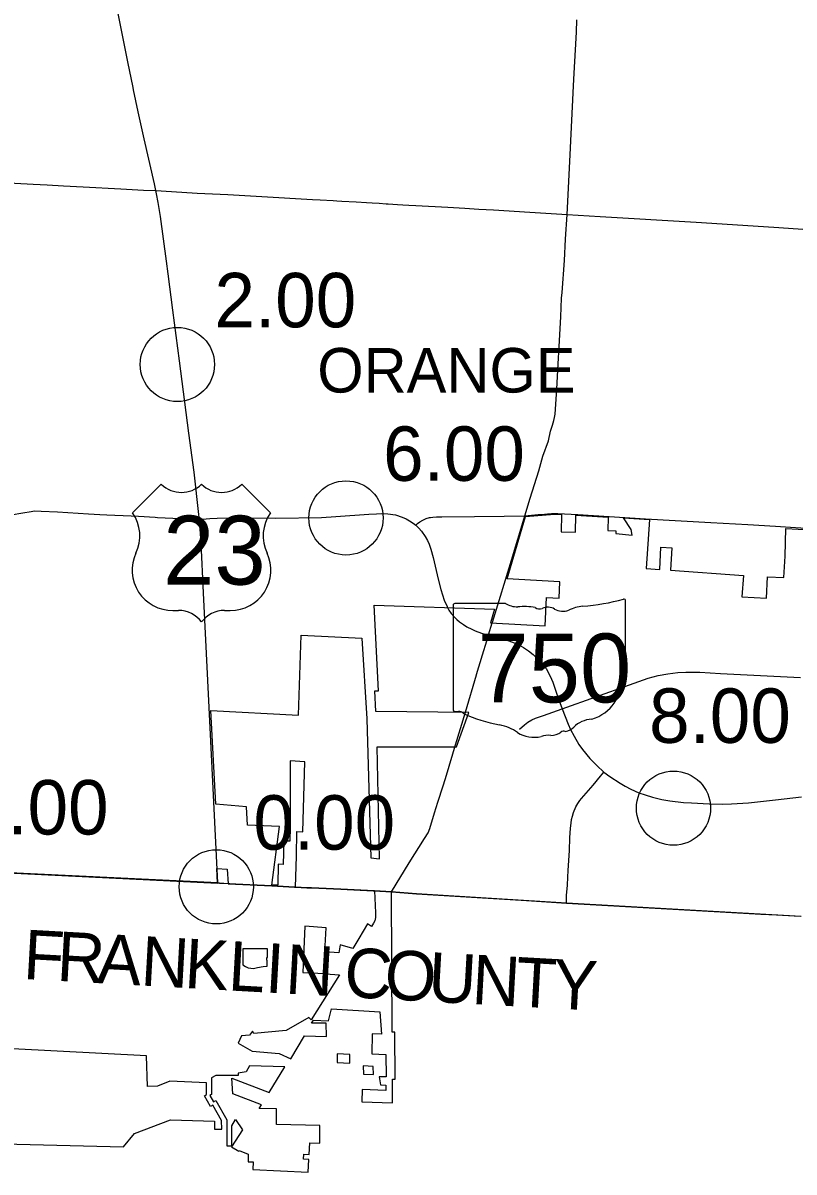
# Model space of a CAD drawing. Extents: x 1597222 to 1925846, y 496284 to 911751.
# Drawn here: x 1820000 to 1835573, y 772839 to 796062 of the extents above; entities that cross this region are included whole.
import ezdxf

# ---------------------------------------------------------------- set-up
doc = ezdxf.new("R2010")
doc.units = 0
for name, color, linetype in [('Default', 7, 'Continuous'), ('GM_X_Adjacent_County_Text', 7, 'Continuous'), ('GM_X_City_Street', 7, 'Continuous'), ('GM_X_Corporation', 7, 'Continuous'), ('GM_X_County', 7, 'Continuous'), ('GM_X_County_Road', 7, 'Continuous'), ('GM_X_State_Route', 7, 'Continuous'), ('GM_X_State_Shield', 7, 'Continuous'), ('GM_X_Township_Road', 7, 'Continuous'), ('GM_X_Township_Text', 7, 'Continuous'), ('GM_X_US_Route', 7, 'Continuous'), ('GM_X_US_Shield', 7, 'Continuous')]:
    doc.layers.add(name, color=color, linetype=linetype)

msp = doc.modelspace()

# ---------------------------------------------------------------- linework, layer by layer
at = {"layer": 'Default'}
for centre in [(1823118, 789161), (1826524, 786059), (1833139, 780193), (1823904, 778604), (1823904, 778604)]:
    msp.add_circle(centre, 750, dxfattribs=at)
at = {"layer": 'GM_X_City_Street'}
for points in [[(1829403, 783698), (1829476, 783942)], [(1829157, 782891), (1829157, 782893), (1829284, 783295), (1829370, 783578), (1829403, 783698)], [(1828738, 781474), (1828935, 782130), (1829157, 782891)], [(1830888, 782204), (1832249, 782689), (1832627, 782818), (1832829, 782872), (1833025, 782905), (1833227, 782932), (1833389, 782939), (1833673, 782939), (1834091, 782912), (1835705, 782831)], [(1830028, 781790), (1830127, 781875), (1830195, 781928), (1830278, 781977), (1830355, 782013), (1830512, 782069), (1830888, 782204)], [(1830981, 778275), (1830981, 778426), (1830998, 778636), (1831007, 778800), (1831013, 778930), (1831036, 779338), (1831048, 779591), (1831061, 779791), (1831069, 779893), (1831081, 779966), (1831097, 780033), (1831121, 780106), (1831168, 780218), (1831205, 780288), (1831244, 780348), (1831278, 780391), (1831372, 780495), (1831514, 780657), (1831665, 780837), (1831734, 780922)], [(1827440, 778500), (1827802, 779087), (1828113, 779577), (1828183, 779692), (1828216, 779780), (1828313, 780101), (1828381, 780311), (1828487, 780643), (1828494, 780666)], [(1823936, 778682), (1823966, 778677), (1824145, 778671)], [(1825505, 778597), (1825506, 778597), (1825736, 778586), (1825825, 778586), (1826422, 778555), (1827074, 778521)], [(1827074, 778521), (1827092, 778520), (1827440, 778500)], [(1827440, 778500), (1827947, 778461), (1830173, 778324)], [(1830173, 778324), (1830981, 778275), (1833959, 778105)], [(1833959, 778105), (1834906, 778051)], [(1834906, 778051), (1835221, 778034)], [(1835221, 778034), (1835694, 778007)]]:
    msp.add_lwpolyline(points, dxfattribs=at)
at = {"layer": 'GM_X_Corporation'}
for points in [[(1818182, 778957), (1823932, 778674), (1823918, 778971), (1824127, 778960), (1824141, 778666), (1825025, 778622), (1825481, 778599), (1825506, 778597), (1825523, 779224), (1825533, 779720), (1825651, 779713), (1825692, 781132), (1825397, 781147), (1825395, 779815), (1825387, 779525), (1825271, 779527), (1825258, 779053), (1825157, 779059), (1825145, 778634), (1825026, 778639), (1825182, 779821), (1824534, 779849), (1824515, 780220), (1823897, 780274), (1823795, 782165), (1825564, 782072), (1825620, 783690), (1826843, 783626), (1826946, 782000), (1827027, 779186), (1827198, 779170), (1827151, 781435), (1828757, 781433), (1829006, 782129), (1827128, 782148), (1827107, 782565), (1827182, 782566), (1827094, 784298), (1829525, 784216), (1829446, 783938), (1830547, 783879), (1830576, 784449), (1830831, 784435), (1830843, 784770), (1829780, 784830), (1830014, 785633), (1830149, 786086), (1830738, 786138), (1830880, 786128), (1830868, 785781), (1831158, 785769), (1831166, 786112), (1831819, 786077), (1831815, 785806), (1831974, 785799), (1831974, 785747), (1832303, 785711), (1832283, 785826), (1832129, 786061), (1832652, 786025), (1832587, 785037), (1832862, 785017), (1832886, 785468), (1833103, 785455), (1833079, 785005), (1834553, 784895), (1834518, 784462), (1835014, 784440), (1835039, 784870), (1835370, 784853), (1835392, 785285), (1835406, 785847), (1835905, 785817)], [(1819605, 773412), (1822027, 773351), (1822253, 773619), (1822982, 773891), (1823867, 773865), (1823869, 773706), (1824013, 773704), (1824009, 773883), (1823832, 774190), (1823788, 774165), (1823663, 774381), (1823707, 774406), (1823707, 774642), (1822967, 774677), (1822717, 774575), (1822517, 774567), (1822492, 775187), (1818880, 775374)]]:
    msp.add_lwpolyline(points, dxfattribs=at)
for points in [[(1824345, 775442), (1824627, 775281), (1825175, 775235), (1825413, 775126), (1825685, 775591), (1826129, 775580), (1826126, 775849), (1825830, 775846), (1825867, 775906), (1826173, 775897), (1826228, 776137), (1827210, 776079), (1827238, 775627), (1827055, 775635), (1827043, 775226), (1827330, 775211), (1827337, 774761), (1827196, 774766), (1827218, 774598), (1827327, 774593), (1827332, 774484), (1826851, 774504), (1826841, 774261), (1827466, 774237), (1827464, 774716), (1827514, 774716), (1827510, 775666), (1827460, 775665), (1827440, 778500), (1827098, 778520), (1827121, 778076), (1827120, 777980), (1827107, 777918), (1827081, 777867), (1827042, 777801), (1826956, 777852), (1826782, 777559), (1826660, 777355), (1826409, 777430), (1826380, 777271), (1826098, 777288), (1826124, 777772), (1825694, 777807), (1825650, 776871), (1826109, 776852), (1826109, 776842), (1826395, 776822), (1825819, 775914), (1825776, 775965), (1825313, 775697), (1824665, 775637), (1824635, 775689), (1824578, 775607), (1824414, 775592)], [(1824442, 777348), (1824442, 777026), (1824494, 776994), (1824548, 776966), (1824656, 776953), (1824740, 776974), (1824853, 776996), (1824934, 777003), (1824934, 777124), (1824922, 777124), (1824922, 777172), (1824942, 777172), (1824942, 777248), (1824942, 777348)], [(1826345, 775056), (1826603, 775041), (1826601, 775212), (1826347, 775231)], [(1823775, 774388), (1823850, 774258), (1823893, 774283), (1824116, 773897), (1824117, 773370), (1824217, 773370), (1824216, 773770), (1824292, 773900), (1824434, 773692), (1824210, 773349), (1824358, 773262), (1824368, 773274), (1824549, 773200), (1824547, 773047), (1824647, 773046), (1824645, 772890), (1825759, 772839), (1825774, 773090), (1825665, 773097), (1825671, 773197), (1825780, 773190), (1825795, 773428), (1825995, 773423), (1825999, 773780), (1825120, 773801), (1825121, 774119), (1824773, 774122), (1824817, 774196), (1824236, 774422), (1824220, 774734), (1824970, 774444), (1825290, 774965), (1824574, 774985), (1824507, 774863), (1824348, 774835), (1824349, 774792), (1823893, 774792), (1823807, 774742), (1823807, 774406)], [(1826873, 774982), (1826880, 774820), (1827079, 774810), (1827071, 774971)]]:
    msp.add_lwpolyline(points, close=True, dxfattribs=at)
at = {"layer": 'GM_X_County'}
msp.add_lwpolyline([(1835717, 778005), (1830981, 778275), (1827947, 778461), (1827440, 778500), (1827092, 778520), (1826422, 778555), (1825825, 778586), (1825736, 778586), (1825506, 778597), (1825481, 778599), (1825025, 778622), (1824141, 778666), (1823966, 778677), (1823936, 778682), (1818187, 778957), (1818151, 778958), (1817250, 778977), (1817214, 778979), (1811853, 779256), (1810377, 779331), (1809792, 779366), (1808550, 779443), (1807438, 779491), (1803704, 779701)], dxfattribs=at)
at = {"layer": 'GM_X_County_Road'}
for points in [[(1830137, 786102), (1830243, 786458), (1830418, 787013), (1830501, 787304), (1830611, 787617), (1830657, 787812), (1830695, 787936), (1830724, 788026), (1830738, 788091), (1830747, 788159), (1830783, 788662), (1830811, 789171), (1830832, 789527), (1830864, 790126), (1830879, 790499), (1830888, 790614), (1830935, 791259), (1830959, 791695), (1830989, 792193), (1831044, 793262), (1831126, 794929), (1831177, 795880), (1831189, 796127)], [(1830137, 786102), (1830408, 786127), (1830473, 786131), (1830595, 786143), (1830674, 786150), (1830727, 786150), (1830805, 786149), (1831205, 786125), (1831840, 786089), (1832575, 786043), (1833895, 785967), (1834638, 785924), (1835200, 785890), (1836012, 785840), (1836343, 785821), (1836473, 785802), (1836589, 785781), (1836648, 785764), (1836710, 785745), (1836767, 785724)], [(1827933, 785912), (1827967, 785947), (1828014, 785981), (1828077, 786017), (1828143, 786045), (1828212, 786066), (1828234, 786070), (1828276, 786074), (1828349, 786080), (1828458, 786082), (1829120, 786088), (1829721, 786095), (1830137, 786102)], [(1829476, 783942), (1829480, 783955), (1829642, 784477), (1829865, 785207), (1829995, 785632), (1830137, 786102)], [(1828494, 780666), (1828554, 780858), (1828738, 781474)]]:
    msp.add_lwpolyline(points, dxfattribs=at)
at = {"layer": 'GM_X_State_Route'}
for points in [[(1815949, 786077), (1816340, 786036), (1817421, 785936), (1817504, 785931), (1817524, 785929), (1818089, 785876), (1818484, 785913), (1818908, 785967), (1819089, 785999), (1819665, 786100), (1819718, 786112), (1820036, 786168), (1820128, 786185), (1820241, 786200), (1820367, 786198), (1820698, 786179), (1821320, 786143), (1821549, 786130)], [(1821549, 786130), (1821693, 786122), (1822187, 786100), (1822334, 786095)], [(1823563, 786025), (1823628, 786033), (1823775, 786046), (1823922, 786053), (1824581, 786061), (1825105, 786055), (1826030, 786067), (1826319, 786087), (1826985, 786136), (1827143, 786145), (1827249, 786149), (1827367, 786145), (1827524, 786120), (1827661, 786077), (1827737, 786044), (1827810, 786003), (1827879, 785955), (1827933, 785912), (1827993, 785854), (1828049, 785790), (1828123, 785685), (1828168, 785604), (1828202, 785526), (1828238, 785425), (1828282, 785261), (1828387, 784818), (1828437, 784614), (1828504, 784396), (1828565, 784270)], [(1822334, 786095), (1822671, 786075), (1822720, 786071), (1823334, 786043), (1823500, 786028), (1823563, 786025)], [(1828565, 784270), (1828569, 784262), (1828604, 784194), (1828648, 784129), (1828708, 784059), (1828761, 784007), (1828819, 783958), (1828895, 783902), (1828967, 783858), (1829063, 783811), (1829136, 783778), (1829258, 783733), (1829403, 783698)], [(1829403, 783698), (1829636, 783627), (1829774, 783588), (1829890, 783548), (1830017, 783494), (1830110, 783438), (1830211, 783374), (1830305, 783298), (1830422, 783188), (1830516, 783076), (1830564, 783014), (1830648, 782859), (1830699, 782739), (1830797, 782459), (1830888, 782204), (1831011, 781894), (1831061, 781782), (1831130, 781649), (1831230, 781480), (1831303, 781382), (1831449, 781200), (1831590, 781057), (1831734, 780922), (1831852, 780832), (1832062, 780696), (1832163, 780638), (1832275, 780576), (1832437, 780506), (1832565, 780463), (1832716, 780413), (1832906, 780365), (1833062, 780340), (1833344, 780306), (1833500, 780298), (1833859, 780281), (1834130, 780274), (1834309, 780283), (1834652, 780302), (1835197, 780361), (1835722, 780425)]]:
    msp.add_lwpolyline(points, dxfattribs=at)
at = {"layer": 'GM_X_State_Shield'}
for p, q in [((1828691, 784294), (1828691, 782181)), ((1828691, 784294), (1828691, 782181)), ((1829744, 784330), (1828725, 784330)), ((1829744, 784330), (1828725, 784330)), ((1832171, 783277), (1832171, 784383)), ((1832171, 783277), (1832171, 784383)), ((1832171, 783277), (1832171, 783277)), ((1832171, 783277), (1832171, 783277))]:
    msp.add_line(p, q, dxfattribs=at)
for centre, major_axis, start_param, end_param in [((1828730, 784298), (40.3, 0), 1.712693, 3.28349), ((1828730, 784298), (40.3, 0), 1.712693, 3.28349), ((1829987, 784576), (391, 0), 4.042523, 4.731795), ((1829987, 784576), (391, 0), 4.042523, 4.731795), ((1830116, 783144), (1404, 0), 1.404758, 1.657858), ((1830116, 783144), (1404, 0), 1.404758, 1.657858), ((1830435, 784309), (113, 0), 3.836095, 5.185415), ((1830435, 784309), (113, 0), 3.836095, 5.185415), ((1830601, 784065), (235, 0), 0.950623, 2.079405), ((1830601, 784065), (235, 0), 0.950623, 2.079405), ((1831402, 783685), (743, 0), 1.699011, 2.107814), ((1831402, 783685), (743, 0), 1.699011, 2.107814), ((1830931, 787211), (3691, 0), 4.814394, 5.042369), ((1830931, 787211), (3691, 0), 4.814394, 5.042369), ((1832132, 784387), (38.7, 0), 6.141152, 7.989035), ((1832132, 784387), (38.7, 0), 6.141152, 7.989035), ((1830904, 784400), (282, 0), 4.081561, 5.145723), ((1830904, 784400), (282, 0), 4.081561, 5.145723), ((1832162, 783196), (60, 0), 1.883978, 3.671073), ((1832162, 783196), (60, 0), 1.883978, 3.671073), ((1831781, 783056), (360, 0), 5.934695, 6.695948), ((1831781, 783056), (360, 0), 5.934695, 6.695948), ((1832130, 783273), (41.5, 0), 5.05454, 6.418171), ((1832130, 783273), (41.5, 0), 5.05454, 6.418171), ((1832310, 782815), (262, 0), 2.387724, 3.262537), ((1832310, 782815), (262, 0), 2.387724, 3.262537), ((1831138, 782674), (923, 0), 5.101752, 6.440018), ((1831138, 782674), (923, 0), 5.101752, 6.440018), ((1828731, 782176), (40.7, 0), 3.00124, 4.508301), ((1828731, 782176), (40.7, 0), 3.00124, 4.508301), ((1828737, 782392), (310, 0), 4.665946, 4.897461), ((1828737, 782392), (310, 0), 4.665946, 4.897461), ((1828800, 782059), (112, 0), 0.519207, 1.627899), ((1828800, 782059), (112, 0), 0.519207, 1.627899), ((1830214, 783957), (2665, 0), 4.195997, 4.488961), ((1830214, 783957), (2665, 0), 4.195997, 4.488961), ((1831527, 781587), (506, 0), 1.647645, 2.488434), ((1831527, 781587), (506, 0), 1.647645, 2.488434), ((1829419, 781231), (834, 0), 0.823519, 1.323587), ((1829419, 781231), (834, 0), 0.823519, 1.323587), ((1830321, 782048), (529, 0), 4.026481, 4.996735), ((1830321, 782048), (529, 0), 4.026481, 4.996735), ((1830665, 781890), (282, 0), 4.691044, 5.507374), ((1830665, 781890), (282, 0), 4.691044, 5.507374), ((1830920, 781685), (79.4, 0), 1.147584, 2.315152), ((1830920, 781685), (79.4, 0), 1.147584, 2.315152), ((1830887, 781976), (298, 0), 4.937069, 5.64225), ((1830887, 781976), (298, 0), 4.937069, 5.64225), ((1830627, 781318), (435, 0), 1.495662, 1.94098), ((1830627, 781318), (435, 0), 1.495662, 1.94098)]:
    msp.add_ellipse(centre, major_axis=major_axis, ratio=0.8, start_param=start_param, end_param=end_param, dxfattribs=at)
at = {"layer": 'GM_X_Township_Road'}
for points in [[(1817878, 792931), (1817995, 792928), (1818106, 792923), (1818482, 792901), (1818787, 792885), (1819262, 792857), (1819834, 792826), (1820206, 792804), (1820486, 792789), (1820816, 792770), (1821218, 792749), (1821979, 792708), (1822434, 792685), (1822684, 792674)], [(1822684, 792674), (1823205, 792644), (1823518, 792626), (1824136, 792597), (1824824, 792554), (1825845, 792496), (1826005, 792489), (1826266, 792474), (1826340, 792468)], [(1826340, 792468), (1826440, 792462), (1826727, 792446), (1826941, 792432), (1827053, 792426), (1827196, 792418), (1827337, 792408), (1827375, 792407), (1827561, 792395), (1827672, 792389), (1827796, 792381), (1827938, 792372), (1828578, 792339), (1828925, 792317), (1829210, 792298), (1829505, 792285), (1830238, 792237), (1830989, 792193)], [(1830989, 792193), (1830989, 792193), (1831659, 792153), (1833599, 792034), (1835168, 791938), (1836243, 791862), (1837317, 791801), (1838966, 791703), (1839258, 791696)], [(1824145, 778671), (1824181, 778670), (1825025, 778622), (1825481, 778599), (1825505, 778597)]]:
    msp.add_lwpolyline(points, dxfattribs=at)
at = {"layer": 'GM_X_US_Route'}
for points in [[(1823552, 786128), (1823460, 786981), (1823349, 787775), (1823161, 789237), (1823026, 790261), (1822930, 790991), (1822896, 791248), (1822775, 792154), (1822731, 792433), (1822700, 792611), (1822684, 792674), (1822657, 792813), (1822450, 793722), (1822328, 794267), (1822235, 794713), (1822226, 794758), (1822121, 795276), (1821937, 796186), (1821679, 797401), (1821619, 797688), (1821461, 798452)], [(1823558, 786077), (1823552, 786128)], [(1823563, 786025), (1823558, 786077)], [(1823936, 778682), (1823645, 784547), (1823597, 785555), (1823580, 785831), (1823563, 786025)]]:
    msp.add_lwpolyline(points, dxfattribs=at)
at = {"layer": 'GM_X_US_Shield'}
for p, q in [((1822794, 786741), (1822214, 786161)), ((1822794, 786741), (1822214, 786161)), ((1824998, 786161), (1824418, 786741)), ((1824998, 786161), (1824418, 786741)), ((1823026, 784189), (1823142, 784189)), ((1823026, 784189), (1823142, 784189)), ((1824070, 784189), (1824186, 784189)), ((1824070, 784189), (1824186, 784189))]:
    msp.add_line(p, q, dxfattribs=at)
for centre, radius, start, end in [((1823200, 787155), 580, 225.573, 314.427), ((1823200, 787155), 580, 225.573, 314.427), ((1824012, 787155), 580, 225.573, 314.427), ((1824012, 787155), 580, 225.573, 314.427), ((1821549, 785695), 812, 334.5471, 35.0009), ((1821549, 785695), 812, 334.5471, 35.0009), ((1825663, 785695), 812, 144.9991, 205.4529), ((1825663, 785695), 812, 144.9991, 205.4529), ((1823017, 785001), 812, 154.8319, 270.6383), ((1823017, 785001), 812, 154.8319, 270.6383), ((1824195, 785001), 812, 269.3617, 25.1681), ((1824195, 785001), 812, 269.3617, 25.1681), ((1823142, 783609), 580, 36.8699, 90), ((1823142, 783609), 580, 36.8699, 90), ((1824070, 783609), 580, 90, 143.1301), ((1824070, 783609), 580, 90, 143.1301)]:
    msp.add_arc(centre, radius, start, end, dxfattribs=at)

# ---------------------------------------------------------------- texts
at = {"layer": 'Default'}
for s, p in [('2.00', (1823868, 789911)), ('6.00', (1827274, 786809)), ('8.00', (1832646, 781513)), ('0.00', (1818866, 779661)), ('0.00', (1824654, 779354))]:
    msp.add_text(s, height=1100, dxfattribs=at).set_placement(p)
at = {"layer": 'GM_X_Adjacent_County_Text'}
for s, rotation, p in [('F', 356.8079, (1819990, 776742)), ('R', 356.8077, (1820666, 776705)), ('A', 356.8076, (1821479, 776659)), ('N', 356.8079, (1822362, 776610)), ('K', 356.8079, (1823245, 776561)), ('L', 356.8078, (1824128, 776511)), ('I', 356.8075, (1824875, 776470)), ('N', 356.8076, (1825284, 776447)), ('C', 356.8078, (1826470, 776381)), ('O', 356.8074, (1827283, 776336)), ('U', 356.8087, (1828166, 776286)), ('N', 356.8166, (1829049, 776237)), ('T', 356.8443, (1829932, 776188)), ('Y', 356.9671, (1830682, 776147))]:
    msp.add_text(s, height=1000, rotation=rotation, dxfattribs=at).set_placement(p)
at = {"layer": 'GM_X_State_Shield'}
msp.add_text('750', height=1392.2, dxfattribs=at).set_placement((1829180, 782330))
msp.add_text('750', height=1392.2, dxfattribs=at).set_placement((1829180, 782330))
at = {"layer": 'GM_X_Township_Text'}
msp.add_text('ORANGE', height=900, rotation=0, dxfattribs=at).set_placement((1825944, 788593))
at = {"layer": 'GM_X_US_Shield'}
msp.add_text('23', height=1392.2, dxfattribs=at).set_placement((1822831, 784711))
msp.add_text('23', height=1392.2, dxfattribs=at).set_placement((1822831, 784711))

doc.saveas('drawing.dxf')
